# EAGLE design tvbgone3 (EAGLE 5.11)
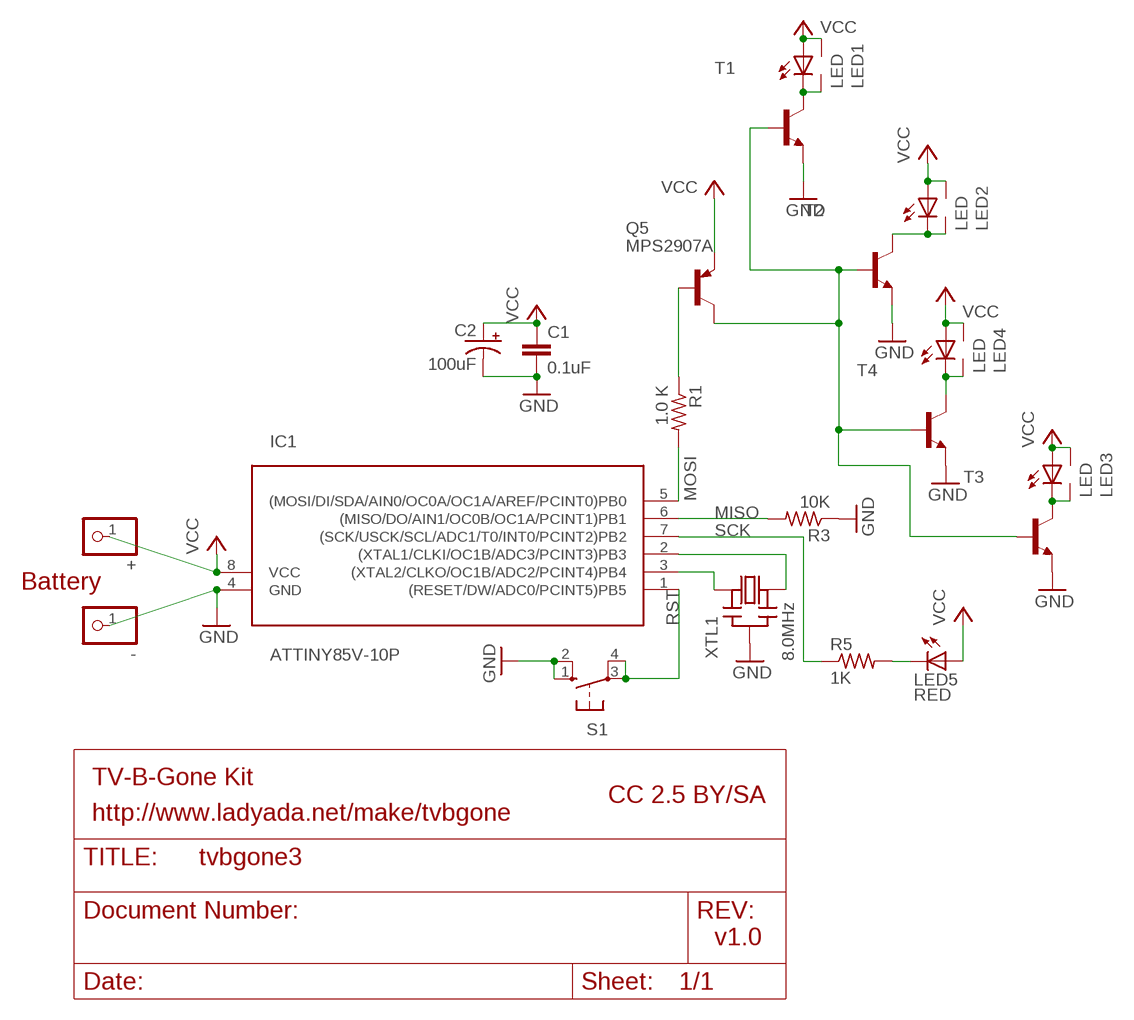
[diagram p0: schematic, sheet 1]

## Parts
+  PINHD-1X1  [1X01]
-  PINHD-1X1  [1X01]
C1  0.1uF  C-EU050-025X075  [C050-025X075]
C2  100uF  CPOL-USE2.5-5  [E2,5-5]
IC1  ATTINY85V-10P  [DIL08]
LED1  LED  [5MM-SIDE]
LED2  LED  [5MM-SIDE]
LED3  LED  [5MM-SIDE]
LED4  LED  [5MM-SIDE]
LED5  RED  LED3MM  [LED3MM]
Q5  MPS2907A  [TO92-CBE]
R1  1.0 K  R-US_0207/10  [0207/10]
R3  10K  R-US_0207/10  [0207/10]
R5  1K  R-US_0207/10  [0207/10]
S1  10-XX  [B3F-10XX]
T1  2N3904-NPN-TO92-EBC  [TO92-EBC]
T2  2N3904-NPN-TO92-EBC  [TO92-EBC]
T3  2N3904-NPN-TO92-EBC  [TO92-EBC]
T4  2N3904-NPN-TO92-EBC  [TO92-EBC]
XTL1  8.0MHz  CERMOSCILL  [CERM_OSC]

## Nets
GND: -.1 C1.2 C2.- IC1.4(GND) R3.1 S1.1(S) S1.2(S1) T1.E T2.E T3.E T4.E XTL1.P$2(GND)
MISO: IC1.6((MISO/DO/AIN1/OC0B/OC1A/PCINT1)PB1) R3.2
MOSI: IC1.5((MOSI/DI/SDA/AIN0/OC0A/OC1A/AREF/PCINT0)PB0) R1.2
N$1: IC1.3((XTAL2/CLKO/OC1B/ADC2/PCINT4)PB4) XTL1.P$1(IN)
N$2: IC1.2((XTAL1/CLKI/OC1B/ADC3/PCINT3)PB3) XTL1.P$3(OUT)
N$3: LED5.K(C) R5.2
N$6: Q5.B R1.1
N$7: LED4.K2(C1) LED4.K(C) T4.C
N$8: LED2.K2(C1) LED2.K(C) T2.C
N$9: LED3.K2(C1) LED3.K(C) T3.C
N$10: Q5.C T1.B T2.B T3.B T4.B
N$11: LED1.K2(C1) LED1.K(C) T1.C
RST: IC1.1((RESET/DW/ADC0/PCINT5)PB5) S1.3(P) S1.4(P1)
SCK: IC1.7((SCK/USCK/SCL/ADC1/T0/INT0/PCINT2)PB2) R5.1
VCC: +.1 C1.1 C2.+ IC1.8(VCC) LED1.A LED1.A2(A1) LED2.A LED2.A2(A1) LED3.A LED3.A2(A1) LED4.A LED4.A2(A1) LED5.A Q5.E

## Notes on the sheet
- Battery
- TV-B-Gone Kit
- CC 2.5 BY/SA
- http://www.ladyada.net/make/tvbgone
- v1.0

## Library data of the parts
+ - = ybox2:PINHD-1X1: PIN HEADER
C1 = rcl:C-EU: CAPACITOR, European symbol
C2 = rcl-ez:CPOL-US: POLARIZED CAPACITOR, American symbol
IC1 = avr:ATTINY85: MICROCONTROLLER 8 Kbytes FLASH 512 bytes EEPROM 512 bytes RAM 4-channel 10 bit ADC USI
LED1-LED4 = tvbgone:LED
LED5 = minimidi:LED: LED
Q5 = transistor-pnp:MPS2907*: PNP Transistror
R1 R3 R5 = rcl-ez:R-US_: RESISTOR, American symbol
S1 = switch-omron:10-XX: OMRON SWITCH; MPN: B3F-1000; OC_FARNELL: 176432; OC_NEWARK: 36M3542
T1-T4 = transistor-neu-to92:*-NPN-: NPN Transistror
XTL1 = digg:CERMOSCILL

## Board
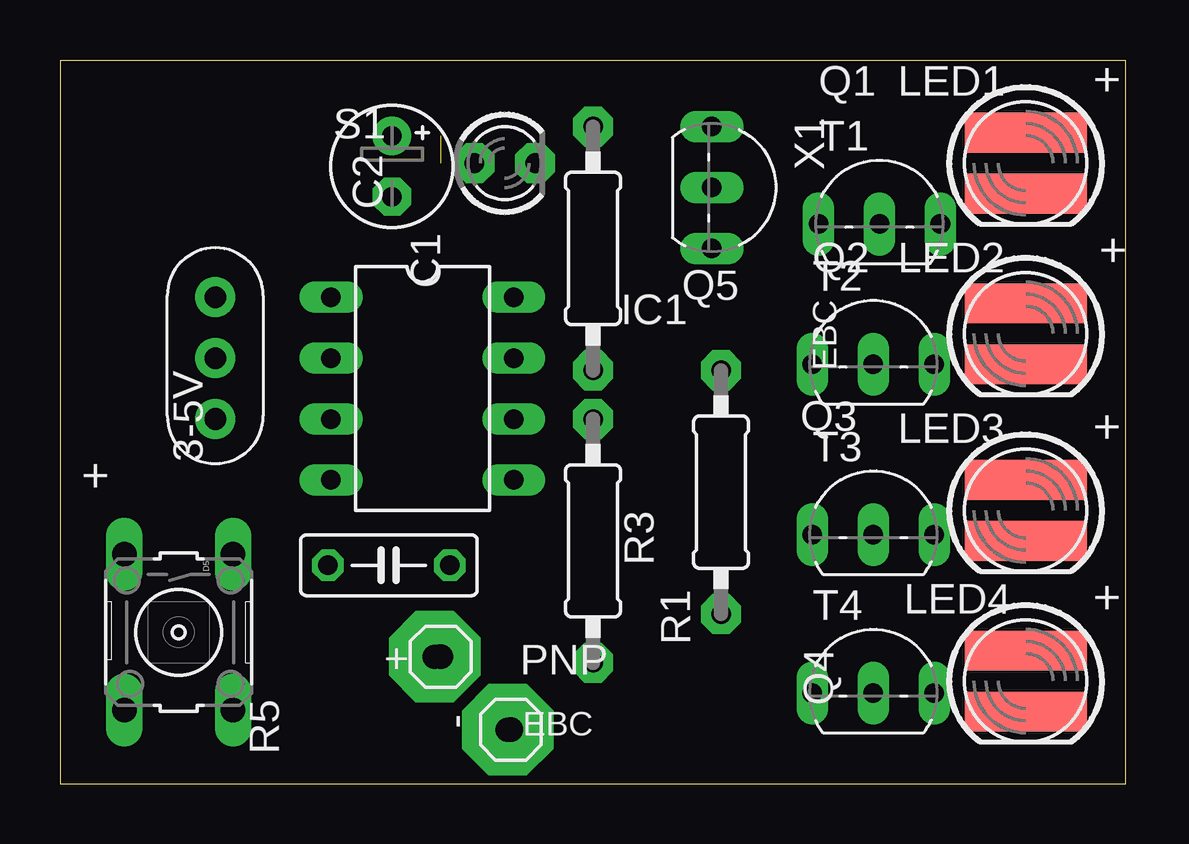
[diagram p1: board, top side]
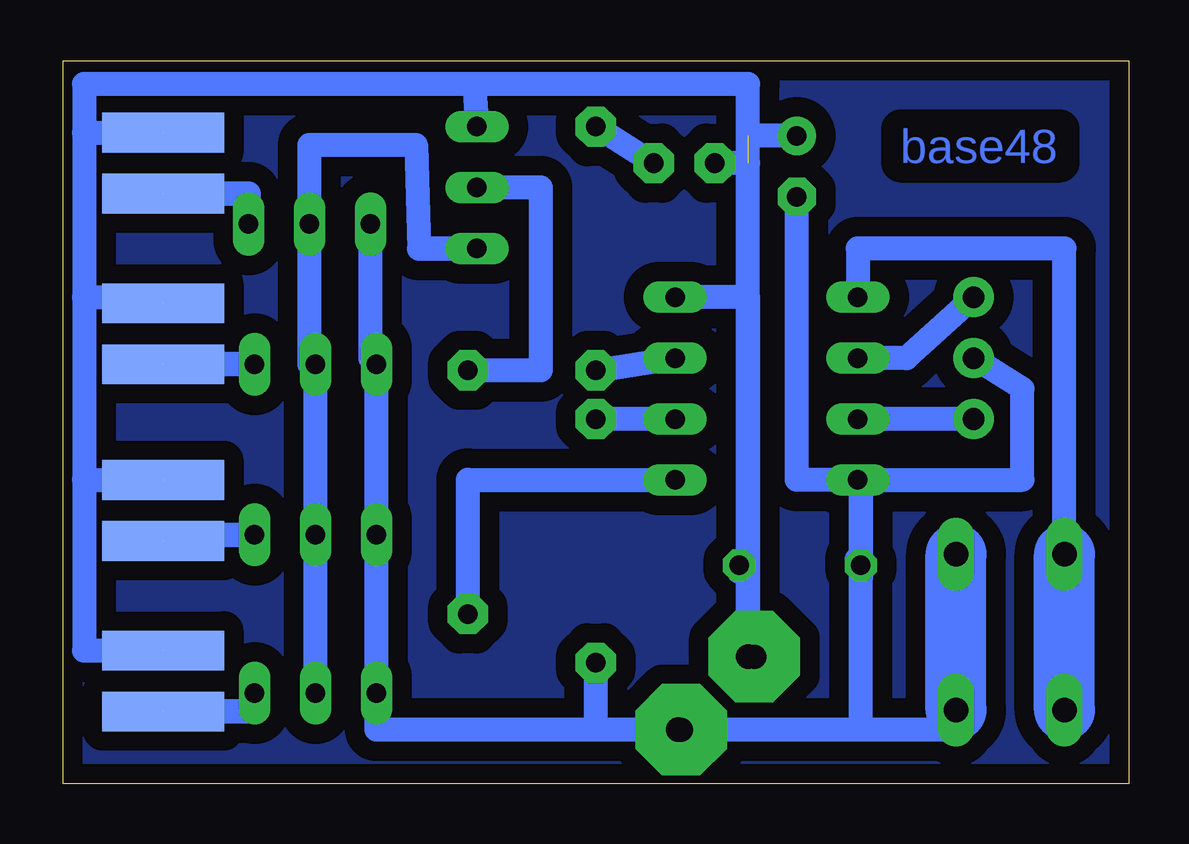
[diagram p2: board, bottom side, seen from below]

Size 44.43 x 30.15 mm. Coordinates in mm from the lower left corner, seen from the top.
Outline: 0,0 44.43,0 44.43,30.15 0,30.15 0,0
Copper layers (1*16): Top 0.035mm / dielectric 1.5mm / Bottom 0.035mm
Design rules "default *": minimum track width 50mil, minimum drill 5mil, track to track 12mil, track to pad 12mil, pad to pad 12mil, via to via 12mil, smd to smd 0mil, copper to edge 16mil, drill to drill 8mil, minimum pad ring 10mil, minimum via ring 8mil, stop-mask expansion 4mil, vias tented up to drill 0mil, thermal gap 10mil

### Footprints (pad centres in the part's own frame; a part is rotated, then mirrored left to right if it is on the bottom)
1X01 = drill 1.016 pad 1.93 octagon: 1 0,0
C050-025X075 = drill 0.813 octagon: 1 -2.54,0; 2 2.54,0
E2,5-5 = drill 0.813 pad 1.6 round: + -1.27,0 | drill 0.813 pad 1.6 octagon: - 1.27,0
DIL08 = drill 0.813 long: 1 -3.81,-3.81; 2 -1.27,-3.81; 3 1.27,-3.81; 4 3.81,-3.81; 5 3.81,3.81; 6 1.27,3.81; 7 -1.27,3.81; 8 -3.81,3.81
5MM-SIDE = smd 1.651 x 5.08: A -1.27,0; K 1.27,0 | smd 1.651 x 5.08 bottom: A2 -1.27,0; K2 1.27,0
LED3MM = drill 0.813 pad 1.676 octagon: A -1.27,0; K 1.27,0
TO92-CBE = drill 0.813 long: B 0,0; C 2.54,0; E -2.54,0
0207/10 = drill 0.813 pad 1.676 octagon: 1 -5.08,0; 2 5.08,0
B3F-10XX = drill 1.016 long: 1 -3.251,2.261; 2 3.251,2.261; 3 -3.251,-2.261; 4 3.251,-2.261
TO92-EBC = drill 0.813 long: B 0,-1.27; C 2.54,-1.27; E -2.54,-1.27
CERM_OSC = drill 0.9 pad 1.676 round: P$1 -2.54,0; P$2 0,0; P$3 2.54,0

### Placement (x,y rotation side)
+  15.87,5.3 0 top
-  18.79,2.25 0 top
C1  13.71,9.11 180 top
C2  13.84,25.74 270 top
IC1  15.11,16.47 270 top
LED1  40.25,25.87 270 top
LED2  40.25,18.76 270 top
LED3  40.25,11.39 270 top
LED4  40.25,4.28 270 top
LED5  18.54,25.87 0 top
Q5  27.17,24.85 270 top
R1  27.55,12.15 270 top
R3  22.22,10.12 90 top
R5  22.22,22.31 90 top
S1  4.95,6.31 270 top
T1  34.16,24.6 0 top
T2  33.9,18.76 0 top
T3  33.9,11.65 0 top
T4  33.9,5.04 0 top
XTL1  6.47,17.74 90 top

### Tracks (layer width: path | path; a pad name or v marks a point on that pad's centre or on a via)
GND  (via drill 1 pad 3.81)
  Bottom 0.406: T2.E 31.62,17.74 | T3.E 31.36,10.88 31.11,11.14 | 11.55,12.66 IC1.4 | 11.07,2.25 11.17,2.25
  Bottom 1: 31.62,17.74 T1.E | 31.36,10.88 T2.E | T3.E T4.E 31.36,2.25 22.22,2.25 | 11.35,9.36 C1.2 11.17,8.6 11.17,2.25 -.1 v18.66,2.25 22.22,2.25 | 22.22,2.25 R3.1 | 11.55,12.66 13.84,12.66 C2.- | S1.2 7.23,3.06 7.23,2.25 11.07,2.25 | IC1.4 4.44,12.66 4.44,16.47 XTL1.P$2
  Bottom 1.016: 11.55,12.66 11.17,12.41 11.17,8.6
  Bottom 2.54: S1.2 S1.1
MISO
  Bottom 1: IC1.6 R3.2
MOSI
  Bottom 1: IC1.5 27.55,12.66 R1.2
N$1
  Bottom 1: XTL1.P$1 IC1.3
N$2
  Bottom 1: XTL1.P$3 9.27,17.74 IC1.2
N$3
  Bottom 1: LED5.K R5.2
N$4  (via drill 1 pad 3.81)
  other vias: 15.62,5.3
N$6
  Bottom 1: Q5.B 24.51,24.85 24.51,17.23 R1.1
N$7  (1 unrouted)
  Bottom 1: T4.C 36.44,3.01
  Bottom 1.016: 36.44,3.01 LED4.K2
N$8  (1 unrouted)
  Bottom 1.016: T2.C LED2.K2
N$9  (1 unrouted)
  Bottom 0.406: 40.25,10.38 LED3.K2
  Bottom 1.016: T3.C 40.25,10.38
N$10
  Bottom 0.406: T2.B 34.16,17.49
  Bottom 1: T4.B T3.B T2.B | 34.16,17.49 T1.B 34.16,26.63 29.71,26.63 29.59,22.31
  Bottom 1.016: 29.59,22.31 Q5.C
N$11  (1 unrouted)
  Bottom 1.016: LED1.K2 36.7,24.6 T1.C
RST
  Bottom 1: IC1.1 11.3,22.31 2.69,22.31 S1.3
  Bottom 2.54: S1.4 S1.3
SCK
  Bottom 1: R5.1 IC1.7
TST
  pour Bottom (isolate 0.813): 0.12,30.19 44.32,30.19 44.32,0.22 0.12,0.22
VCC  (5 unrouted)
  Bottom 0.406: 40.51,20.28 LED2.A2
  Bottom 1: LED4.A2 43.56,5.55 43.56,12.66 | 43.56,20.28 43.56,12.66 | 43.56,27.14 43.56,20.28 | 43.56,27.14 LED1.A2 | 43.56,20.28 40.51,20.28 | 43.56,12.66 LED3.A2 | 27.3,29.17 Q5.E | 27.3,29.17 43.56,29.17 43.56,27.14 | 27.3,29.17 15.87,29.17 15.87,25.87 | IC1.8 15.87,20.28 15.87,25.87 | 15.87,25.87 LED5.A | C2.+ 15.87,27.01
  Bottom 1.016: 15.87,20.28 15.87,8.85 16.25,8.85 C1.1 15.87,9.11 +.1

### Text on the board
Bottom: base48
tPlace: Q1 | LED1 | + | S1 | X1 | C2 | + | C1 | Q2 | LED2 | IC1 | EBC | Q3 | LED3 | + | 3-5V | + | D5 | LED4 | + | PNP | EBC | Q4 | R5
